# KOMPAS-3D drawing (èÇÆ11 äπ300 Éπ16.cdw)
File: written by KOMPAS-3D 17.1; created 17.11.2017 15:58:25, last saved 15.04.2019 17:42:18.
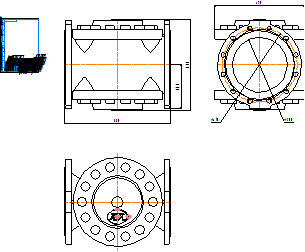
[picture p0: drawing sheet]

Sheet 1: A4, portrait

Title block, sheet 1: name: КАТ11 Ду300 Ру16; material: Внимание! Данный продукт является объектом авторского права ООО «Торговый Дом АДЛ». / Запрещается изменение, копирование, распространение / (в том числе путем копирования на другие сайты и ресурсы в Интернете) / или любое иное использование информации и объектов без предварительного / согласия правообладателя (ООО «Торговый Дом АДЛ»).; mass: 12,4; sheets: 1; organisation: ООО "Торговый дом АДЛ"; sheet format: A4; stored path: \\adlc.lan\data\АДЛ_ПКД\3D-модели\ADL production\Клапаны КАТ ГРАНРЕГ\КАТ11\KOMPAS 2D\КАТ11 Ду300 Ру16.cdw

Views: Вид 1, Проекционный вид 2, Проекционный вид 3
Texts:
  kka
  adl
Dimensions and other numbers on the sheet: 580; 240; 495; 410; 490; 300; 1:1; 1; 12,4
